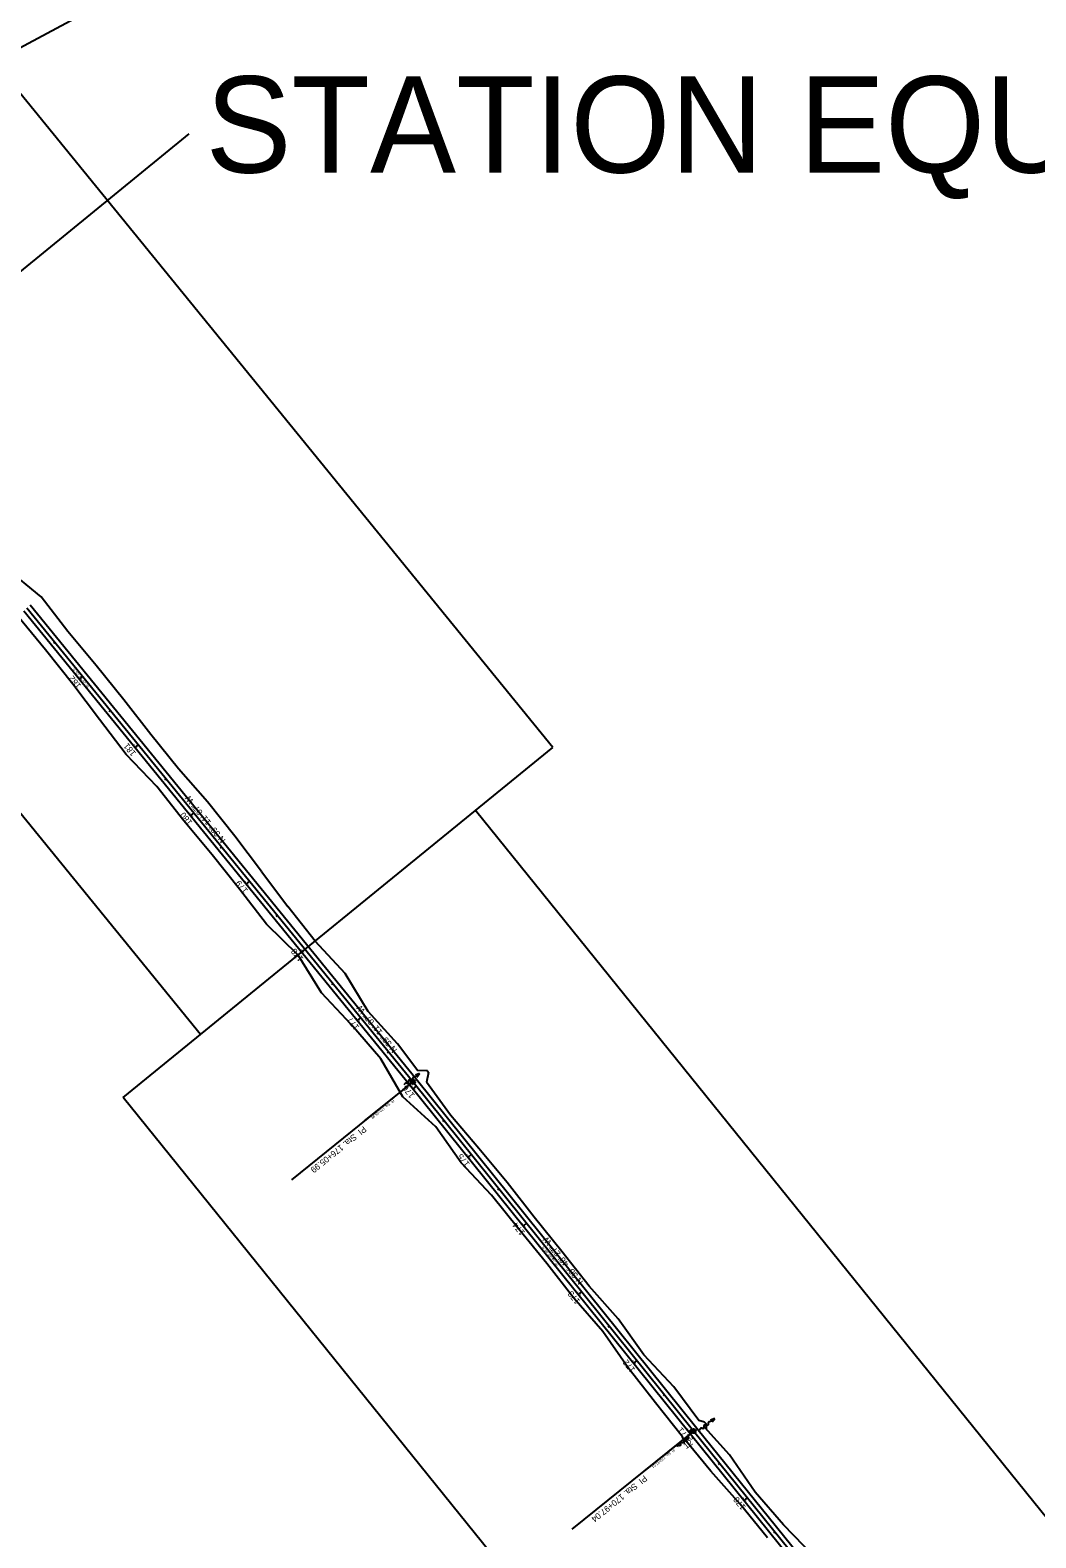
# Model space of a CAD drawing. Extents: x 2399886 to 2513208, y 556821 to 592417.
# Drawn here: x 2435555 to 2436698, y 566507 to 568219 of the extents above; entities that cross this region are included whole.
import ezdxf

# ---------------------------------------------------------------- set-up
doc = ezdxf.new("R2010")
doc.units = 0
for name, color, linetype in [('GM_X_Interchange_Ramps', 7, 'Continuous'), ('GM_X_Major_River', 7, 'Continuous'), ('GM_X_Major_River_Text', 7, 'Continuous'), ('GM_X_Section', 7, 'Continuous'), ('GM_X_Township', 7, 'Continuous'), ('GM_X_Unincorporated', 7, 'Continuous'), ('GM_X_US_Shield', 7, 'Continuous'), ('SH_Data', 7, 'Continuous'), ('TX_P_1', 7, 'Continuous')]:
    doc.layers.add(name, color=color, linetype=linetype)

msp = doc.modelspace()

# ---------------------------------------------------------------- linework, layer by layer
at = {"layer": 'GM_X_Interchange_Ramps'}
for p, q in [((2435567.7, 567576.1), (2435527.3, 567609.4)), ((2435598, 567536.4), (2435567.7, 567576.1)), ((2435572.7, 567515.7), (2435541, 567554.4)), ((2435630.1, 567498), (2435598, 567536.4)), ((2435603.9, 567476.6), (2435572.7, 567515.7)), ((2435661.5, 567459.1), (2435630.1, 567498)), ((2435633.9, 567436.6), (2435603.9, 567476.6)), ((2435692.4, 567419.7), (2435661.5, 567459.1)), ((2435664.3, 567396.9), (2435633.9, 567436.6)), ((2435723.6, 567380.7), (2435692.4, 567419.7)), ((2435699.1, 567360.7), (2435664.3, 567396.9)), ((2435756.9, 567343.3), (2435723.6, 567380.7)), ((2435730, 567321.4), (2435699.1, 567360.7)), ((2435787.7, 567304), (2435756.9, 567343.3)), ((2435762, 567283), (2435730, 567321.4)), ((2435818.1, 567264.2), (2435787.7, 567304)), ((2435787.7, 567304), (2435787.7, 567304)), ((2435793.2, 567243.9), (2435762, 567283)), ((2435818.1, 567264.2), (2435848.1, 567224.2)), ((2435823.8, 567204.3), (2435793.2, 567243.9)), ((2435835.9, 567214.2), (2435835.9, 567214.2)), ((2435878.9, 567184.8), (2435848.1, 567224.2)), ((2435848.1, 567224.2), (2435848.1, 567224.2)), ((2435859.9, 567169.1), (2435823.8, 567204.3)), ((2435913, 567148.1), (2435878.9, 567184.8)), ((2435886.3, 567126.3), (2435859.9, 567169.1)), ((2435939.3, 567104.9), (2435913, 567148.1)), ((2435920.2, 567089.8), (2435886.3, 567126.3)), ((2435972.6, 567068.2), (2435939.3, 567104.9)), ((2435953.6, 567051.4), (2435920.2, 567089.8)), ((2435995.9, 567037.7), (2435972.6, 567068.2)), ((2436006.2, 567038), (2435995.9, 567037.7)), ((2436008, 567035.6), (2436005.6, 567024.9)), ((2436032.8, 566987.3), (2436005.6, 567024.9)), ((2436006.2, 567038), (2436008, 567035.6)), ((2436065, 566949.5), (2436032.8, 566987.3)), ((2436097.1, 566911), (2436065, 566949.5)), ((2436127.8, 566871.4), (2436097.1, 566911)), ((2436159.2, 566832.6), (2436127.8, 566871.4)), ((2436190.3, 566793.2), (2436159.2, 566832.6)), ((2436223.5, 566756), (2436190.3, 566793.2)), ((2436252.5, 566715.2), (2436223.5, 566756)), ((2436234.9, 566700.2), (2436205.8, 566741.7)), ((2436265.7, 566660.8), (2436234.9, 566700.2)), ((2436234.9, 566700.2), (2436234.9, 566700.2)), ((2436286.6, 566678.9), (2436252.5, 566715.2)), ((2436315, 566640.5), (2436286.6, 566678.9)), ((2436296.4, 566622.1), (2436265.7, 566660.8)), ((2436321.6, 566638.7), (2436315, 566640.5)), ((2436321.6, 566638.7), (2436322.8, 566637.1)), ((2436349.7, 566601.7), (2436321.8, 566632.6)), ((2436322.8, 566637.1), (2436323.3, 566630.9)), ((2436296.6, 566621.9), (2436296.4, 566622.1)), ((2436297.1, 566620), (2436296.6, 566621.9)), ((2436298.3, 566618.4), (2436297.1, 566620)), ((2436298.3, 566618.4), (2436300.7, 566616.9)), ((2436328.8, 566583.2), (2436300.7, 566616.9)), ((2436379.1, 566559), (2436349.7, 566601.7)), ((2436361.8, 566545.6), (2436328.8, 566583.2)), ((2436393, 566507.3), (2436361.8, 566545.6)), ((2436361.8, 566545.6), (2436361.8, 566545.6)), ((2436379.1, 566559), (2436379.1, 566559))]:
    msp.add_line(p, q, dxfattribs=at)
for points in [[(2436205.8, 566741.7), (2436172.9, 566779.4), (2436142.3, 566819), (2436110.6, 566857.7), (2436079.3, 566896.6), (2436044.8, 566933.1), (2436016.2, 566974.2), (2435978.5, 567008.1), (2435953.6, 567051.4)], [(2436663, 566211.2), (2436631.5, 566250), (2436600.9, 566289.5), (2436568.1, 566327.4), (2436535.1, 566365), (2436504.9, 566404.8), (2436473.8, 566444), (2436446.2, 566486), (2436411.1, 566521.9), (2436379.1, 566559)]]:
    msp.add_lwpolyline(points, dxfattribs=at)
at = {"layer": 'GM_X_Major_River'}
for p, q in [((2435990.1, 567025.1), (2435551.6, 567563)), ((2435614.8, 567485.5), (2435610.9, 567482.3)), ((2435677.9, 567408), (2435674.1, 567404.8)), ((2435741.1, 567330.5), (2435737.2, 567327.3)), ((2435804.3, 567253), (2435800.4, 567249.8)), ((2435867.5, 567175.5), (2435863.6, 567172.3)), ((2435930.7, 567097.9), (2435926.8, 567094.8)), ((2436309, 566628.5), (2435990.1, 567025.1)), ((2435988.1, 567023.5), (2435852, 566914)), ((2435993.8, 567020.4), (2435989.9, 567017.3)), ((2436056.5, 566942.5), (2436052.6, 566939.3)), ((2436119.2, 566864.6), (2436115.3, 566861.4)), ((2436181.8, 566786.6), (2436177.9, 566783.5)), ((2436244.5, 566708.7), (2436240.6, 566705.6)), ((2436307.2, 566630.8), (2436303.3, 566627.6)), ((2436307.1, 566626.9), (2436170.8, 566517)), ((2436685.5, 566161.7), (2436309, 566628.5)), ((2436369.9, 566552.9), (2436366.1, 566549.8))]:
    msp.add_line(p, q, dxfattribs=at)
for centre in [(2435990.1, 567025.1), (2436309, 566628.5)]:
    msp.add_circle(centre, 2.5, dxfattribs=at)
at = {"layer": 'GM_X_Major_River_Text'}
for p, q in [((2436149.1, 567405), (2435334.1, 568404.7)), ((2435702.2, 568284.1), (2435238, 568035.9)), ((2435748.9, 567078.8), (2434853.1, 568177.7)), ((2435361.4, 567796.4), (2435736, 568101.8)), ((2435661.1, 567007.2), (2436149.1, 567405)), ((2436921.3, 566268.2), (2436061.3, 567333.4)), ((2436562.3, 565891), (2435661.1, 567007.2))]:
    msp.add_line(p, q, dxfattribs=at)
at = {"layer": 'GM_X_Section'}
for p, q in [((2435986.2, 567021.9), (2435547.9, 567559.7)), ((2435993.9, 567028.2), (2435555.3, 567566.4)), ((2436312.9, 566631.6), (2435994, 567028.2)), ((2436305.1, 566625.3), (2435986.2, 567021.9)), ((2436689.1, 566165.1), (2436312.9, 566631.6)), ((2436681.8, 566158.3), (2436305.1, 566625.3))]:
    msp.add_line(p, q, dxfattribs=at)
at = {"layer": 'GM_X_Township'}
for p, q in [((2435990.1, 567025.1), (2435551.6, 567563)), ((2435990, 567025), (2435990.1, 567025.1)), ((2435990, 567025.1), (2435990.1, 567025)), ((2436309, 566628.5), (2435990.1, 567025.1)), ((2436309, 566628.4), (2436309.1, 566628.5)), ((2436309, 566628.5), (2436309.1, 566628.4)), ((2436685.5, 566161.7), (2436309, 566628.5))]:
    msp.add_line(p, q, dxfattribs=at)
at = {"layer": 'GM_X_US_Shield'}
for p, q in [((2435997.8, 567034.5), (2435993, 567032.7)), ((2435994.5, 567030.5), (2435997.8, 567034.5)), ((2436333.2, 566643), (2436328.4, 566641)), ((2436330.1, 566638.9), (2436333.2, 566643))]:
    msp.add_line(p, q, dxfattribs=at)
for points in [[(2435997.8, 567034.5), (2435993.6, 567031.5), (2435991.6, 567030.6), (2435990.3, 567030.3), (2435989.5, 567026.8), (2435985.5, 567027.2), (2435984.2, 567023), (2435982.8, 567023.8), (2435980, 567021.7)], [(2436333.2, 566643), (2436329.1, 566639.9), (2436327.2, 566639), (2436325.9, 566638.6), (2436325.2, 566635.1), (2436321.2, 566635.3), (2436320, 566631.2), (2436318.5, 566631.8), (2436315.8, 566629.7)]]:
    msp.add_spline(points, degree=3, dxfattribs=at)
at = {"layer": 'SH_Data'}
for p, q in [((2435990.1, 567025.1), (2435551.6, 567563)), ((2435583.2, 567524.3), (2435581.6, 567523)), ((2435614.8, 567485.5), (2435613.2, 567484.2)), ((2435646.3, 567446.7), (2435644.8, 567445.5)), ((2435677.9, 567408), (2435676.4, 567406.7)), ((2435709.5, 567369.2), (2435708, 567368)), ((2435741.1, 567330.5), (2435739.6, 567329.2)), ((2435772.7, 567291.7), (2435771.2, 567290.5)), ((2435804.3, 567253), (2435802.8, 567251.7)), ((2435835.9, 567214.2), (2435834.3, 567212.9)), ((2435867.5, 567175.5), (2435865.9, 567174.2)), ((2435899.1, 567136.7), (2435897.5, 567135.4)), ((2435930.7, 567097.9), (2435929.1, 567096.7)), ((2435962.3, 567059.2), (2435960.7, 567057.9)), ((2435989.3, 567024.4), (2435934.8, 566980.7)), ((2436309, 566628.5), (2435990.1, 567025.1)), ((2435993.8, 567020.4), (2435992.3, 567019.2)), ((2436025.2, 566981.4), (2436023.6, 566980.2)), ((2436056.5, 566942.5), (2436054.9, 566941.2)), ((2436087.8, 566903.5), (2436086.3, 566902.3)), ((2436119.2, 566864.6), (2436117.6, 566863.3)), ((2436150.5, 566825.6), (2436148.9, 566824.3)), ((2436181.8, 566786.6), (2436180.3, 566785.4)), ((2436213.2, 566747.7), (2436211.6, 566746.4)), ((2436244.5, 566708.7), (2436242.9, 566707.5)), ((2436275.8, 566669.7), (2436274.3, 566668.5)), ((2436307.2, 566630.8), (2436305.6, 566629.5)), ((2436308.3, 566627.8), (2436253.8, 566583.9)), ((2436685.5, 566161.7), (2436309, 566628.5)), ((2436338.6, 566591.9), (2436337, 566590.6)), ((2436369.9, 566552.9), (2436368.4, 566551.7)), ((2436401.3, 566514), (2436399.8, 566512.8))]:
    msp.add_line(p, q, dxfattribs=at)
for centre in [(2435990.1, 567025.1), (2436309, 566628.5)]:
    msp.add_circle(centre, 1, dxfattribs=at)
at = {"layer": 'TX_P_1'}
for p, q in [((2436300.4, 566619.8), (2436304.2, 566621.4)), ((2436301.7, 566618.1), (2436300.4, 566619.8)), ((2436304.2, 566621.4), (2436301.7, 566618.1))]:
    msp.add_line(p, q, dxfattribs=at)
msp.add_spline([(2436301, 566619), (2436300.9, 566618.9), (2436299.4, 566618.2), (2436298.3, 566617.8), (2436297.8, 566615.1), (2436294.6, 566615.3), (2436293.6, 566611.9), (2436292.5, 566612.5), (2436290.3, 566610.8)], degree=3, dxfattribs=at)

# ---------------------------------------------------------------- texts
at = {"layer": 'GM_X_Major_River'}
for s, rotation, p in [('182', 129.1854, (2435613.6, 567475.1)), ('181', 129.1854, (2435676, 567398.5)), ('N 39%%d 11\' 07" W', 129.1854, (2435777.7, 567299.9)), ('180', 129.1854, (2435740, 567319.9)), ('179', 129.1854, (2435803.1, 567242.6)), ('178', 129.1854, (2435866.2, 567165.2)), ('N 39%%d 11\' 07" W', 129.1854, (2435972.6, 567061.6)), ('177', 129.1854, (2435929.6, 567087.4)), ('176', 128.8074, (2435992.6, 567010)), ('PI  Sta. 176+05.99', 218.8074, (2435933.8, 566975.3)), ('175', 128.8074, (2436055.2, 566932.1)), ('174', 128.8074, (2436117.8, 566854.2)), ('N 38%%d 48\' 27" W', 128.8074, (2436184.1, 566798.4)), ('173', 128.8074, (2436180.6, 566776.2)), ('172', 128.8074, (2436243.2, 566698.4)), ('171', 128.8074, (2436305.1, 566621.3)), ('PI  Sta. 170+97.04', 218.8816, (2436252.8, 566578.7)), ('170', 128.8816, (2436368.8, 566542.5))]:
    msp.add_text(s, height=7, rotation=rotation, dxfattribs=at).set_placement(p)
at = {"layer": 'GM_X_Major_River_Text'}
msp.add_text('STATION EQUATION HERE', height=109.375, dxfattribs=at).set_placement((2435754.6, 568057.7))
at = {"layer": 'GM_X_Township'}
for s, p in [('TEMP67', (2435989.3, 567025.1)), ('TEMP66', (2436308.3, 566628.5))]:
    msp.add_text(s, height=0.14, dxfattribs=at).set_placement(p)
at = {"layer": 'GM_X_Unincorporated'}
msp.add_text('12"', height=7, rotation=37.3241, dxfattribs=at).set_placement((2436300.7, 566607.8))
at = {"layer": 'SH_Data'}
for s, rotation, p in [('N 39%%d 11\' 07" W', 309.1854, (2435603, 567493.3)), ('182', 129.1854, (2435614.3, 567481.3)), ('181', 129.1854, (2435677.2, 567404.2)), ('180', 129.1854, (2435740.7, 567326.3)), ('179', 129.1854, (2435803.8, 567248.8)), ('178', 129.1854, (2435867, 567171.3)), ('177', 129.1854, (2435930.2, 567093.7)), ('176', 128.8074, (2435993.3, 567016.2)), ('PI  Sta. 176+05.99', 218.8074, (2435967.6, 567005.2)), ('175', 128.8074, (2436056, 566938.3)), ('174', 128.8074, (2436118.6, 566860.4)), ('N 38%%d 48\' 27" W', 308.8074, (2436136.1, 566836.8)), ('173', 128.8074, (2436181.3, 566782.5)), ('172', 128.8074, (2436244, 566704.6)), ('171', 128.8074, (2436306.4, 566627)), ('PI  Sta. 170+97.04', 218.8816, (2436286.6, 566608.6)), ('170', 128.8816, (2436369.5, 566548.7))]:
    msp.add_text(s, height=2.8, rotation=rotation, dxfattribs=at).set_placement(p)

doc.saveas('drawing.dxf')
